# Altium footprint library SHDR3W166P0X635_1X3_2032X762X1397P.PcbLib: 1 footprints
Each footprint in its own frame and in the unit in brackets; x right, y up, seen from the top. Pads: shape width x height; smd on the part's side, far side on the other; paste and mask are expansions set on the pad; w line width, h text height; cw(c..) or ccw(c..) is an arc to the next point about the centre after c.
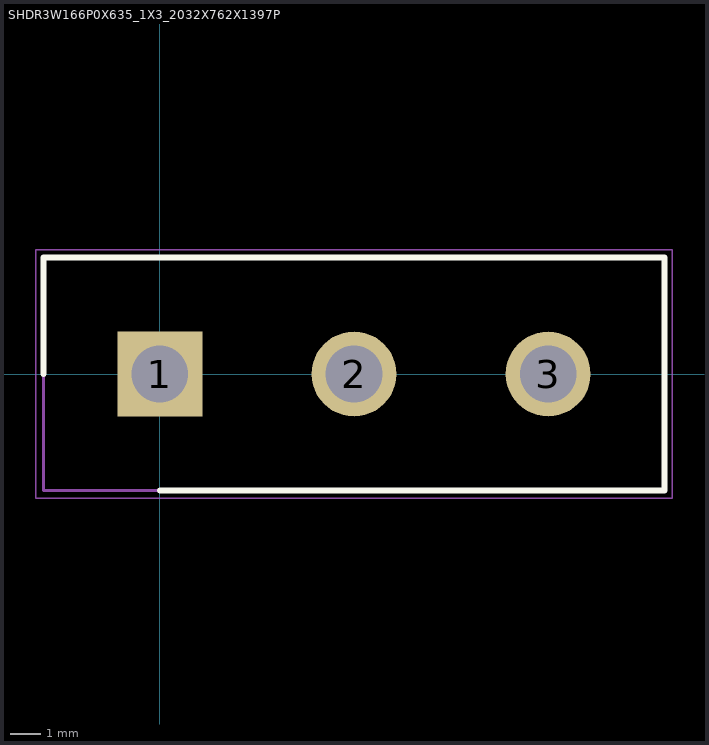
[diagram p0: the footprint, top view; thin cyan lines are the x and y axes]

## SHDR3W166P0X635_1X3_2032X762X1397P [mm]
pads (3):
  rect 2.775x2.775 / inner round 2.775 / far side rect 2.775x2.775 hole 1.85: 1(0,0)
  round 2.775 hole 1.85: 2(6.35,0) 3(12.7,0)
Top Overlay:
  lines w0.2: -3.81,0 -3.81,3.81 16.51,3.81 16.51,-3.81 0,-3.81
Mechanical 15:
  lines w0.1: -3.81,-3.81 -3.81,3.81 16.51,3.81 16.51,-3.81 -3.81,-3.81
Mechanical 20:
  lines w0.05: -4.06,-4.06 -4.06,4.06 16.76,4.06 16.76,-4.06 -4.06,-4.06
